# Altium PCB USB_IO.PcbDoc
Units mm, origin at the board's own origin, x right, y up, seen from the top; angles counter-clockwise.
Board outline 43.86 x 40 mm, 2 copper layers (Top Layer, Bottom Layer); 35 components, 51 nets, 147 pads, 74 vias.
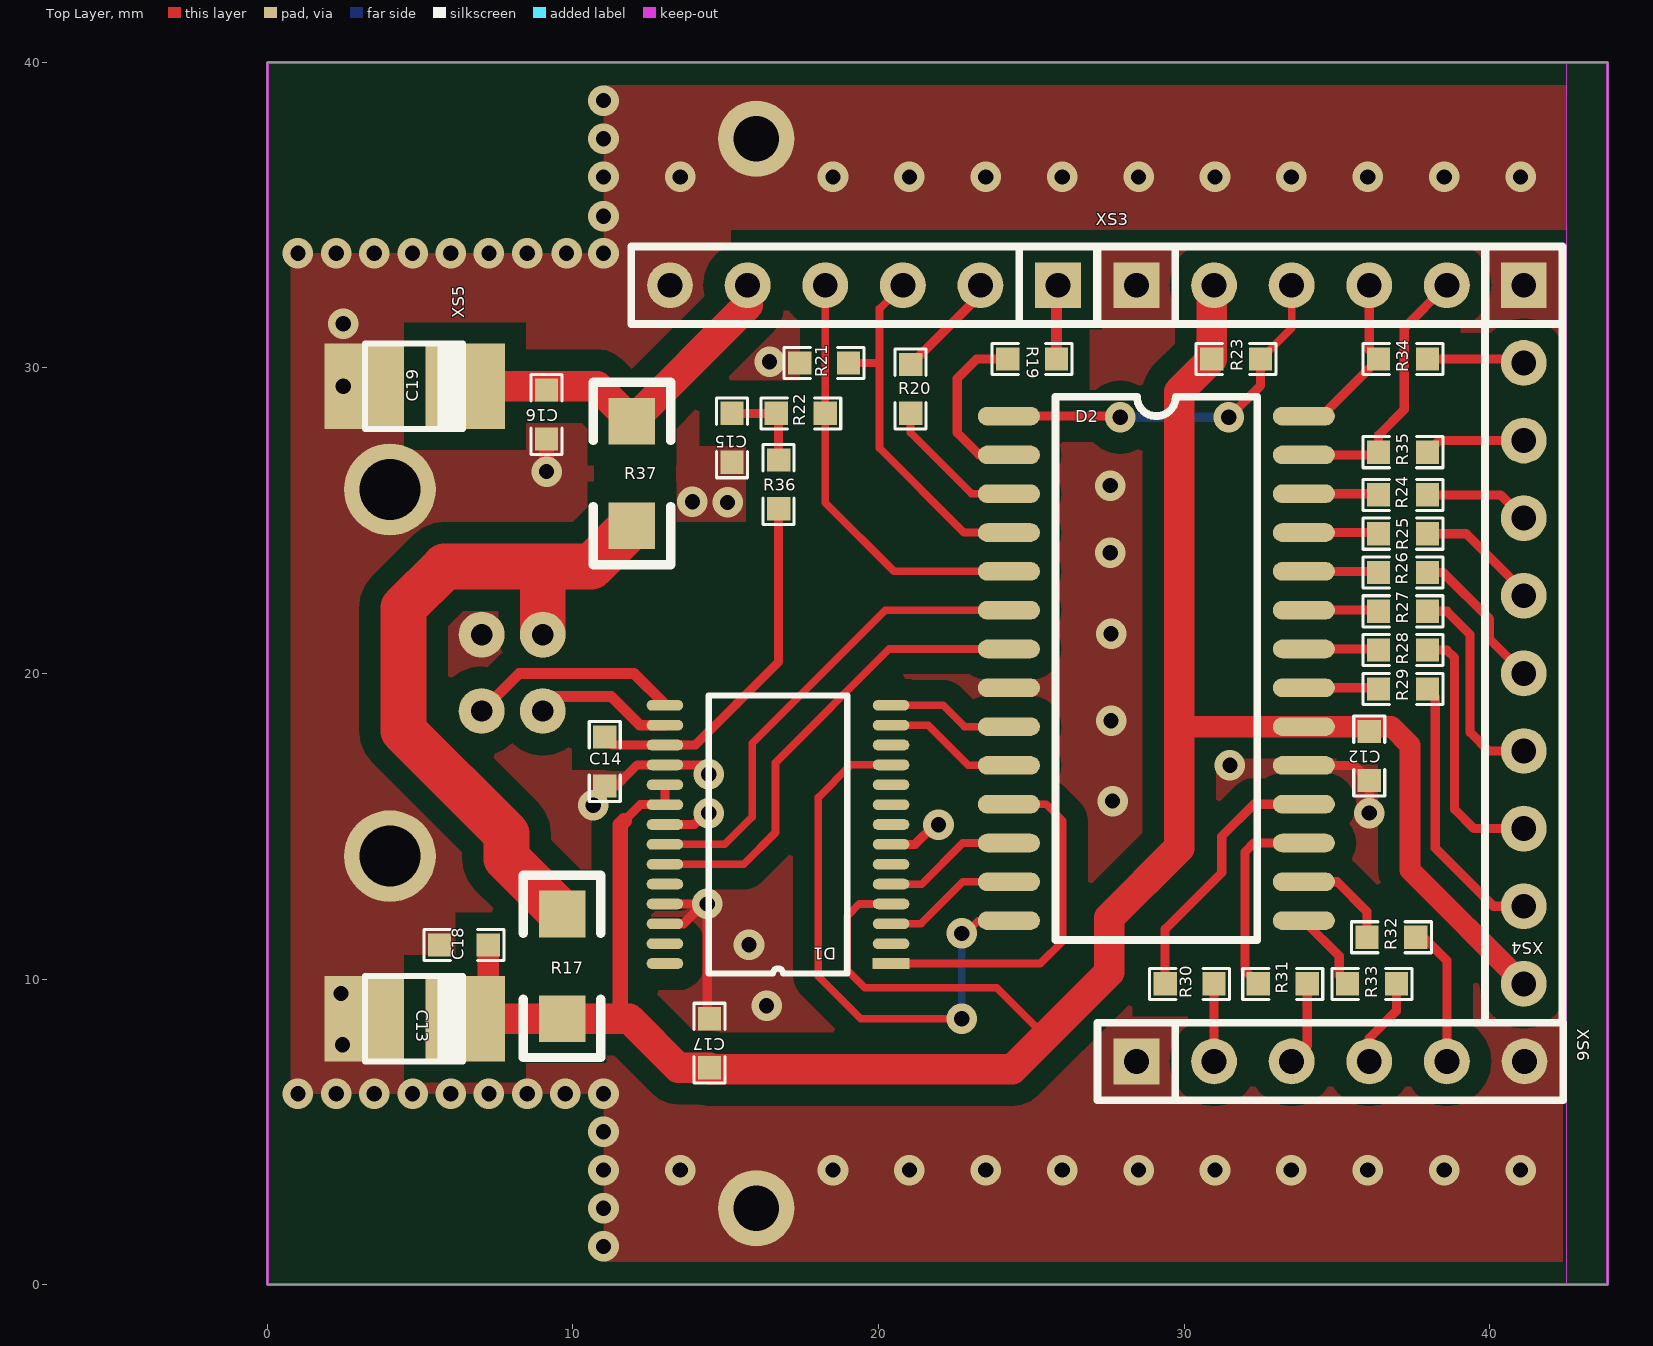
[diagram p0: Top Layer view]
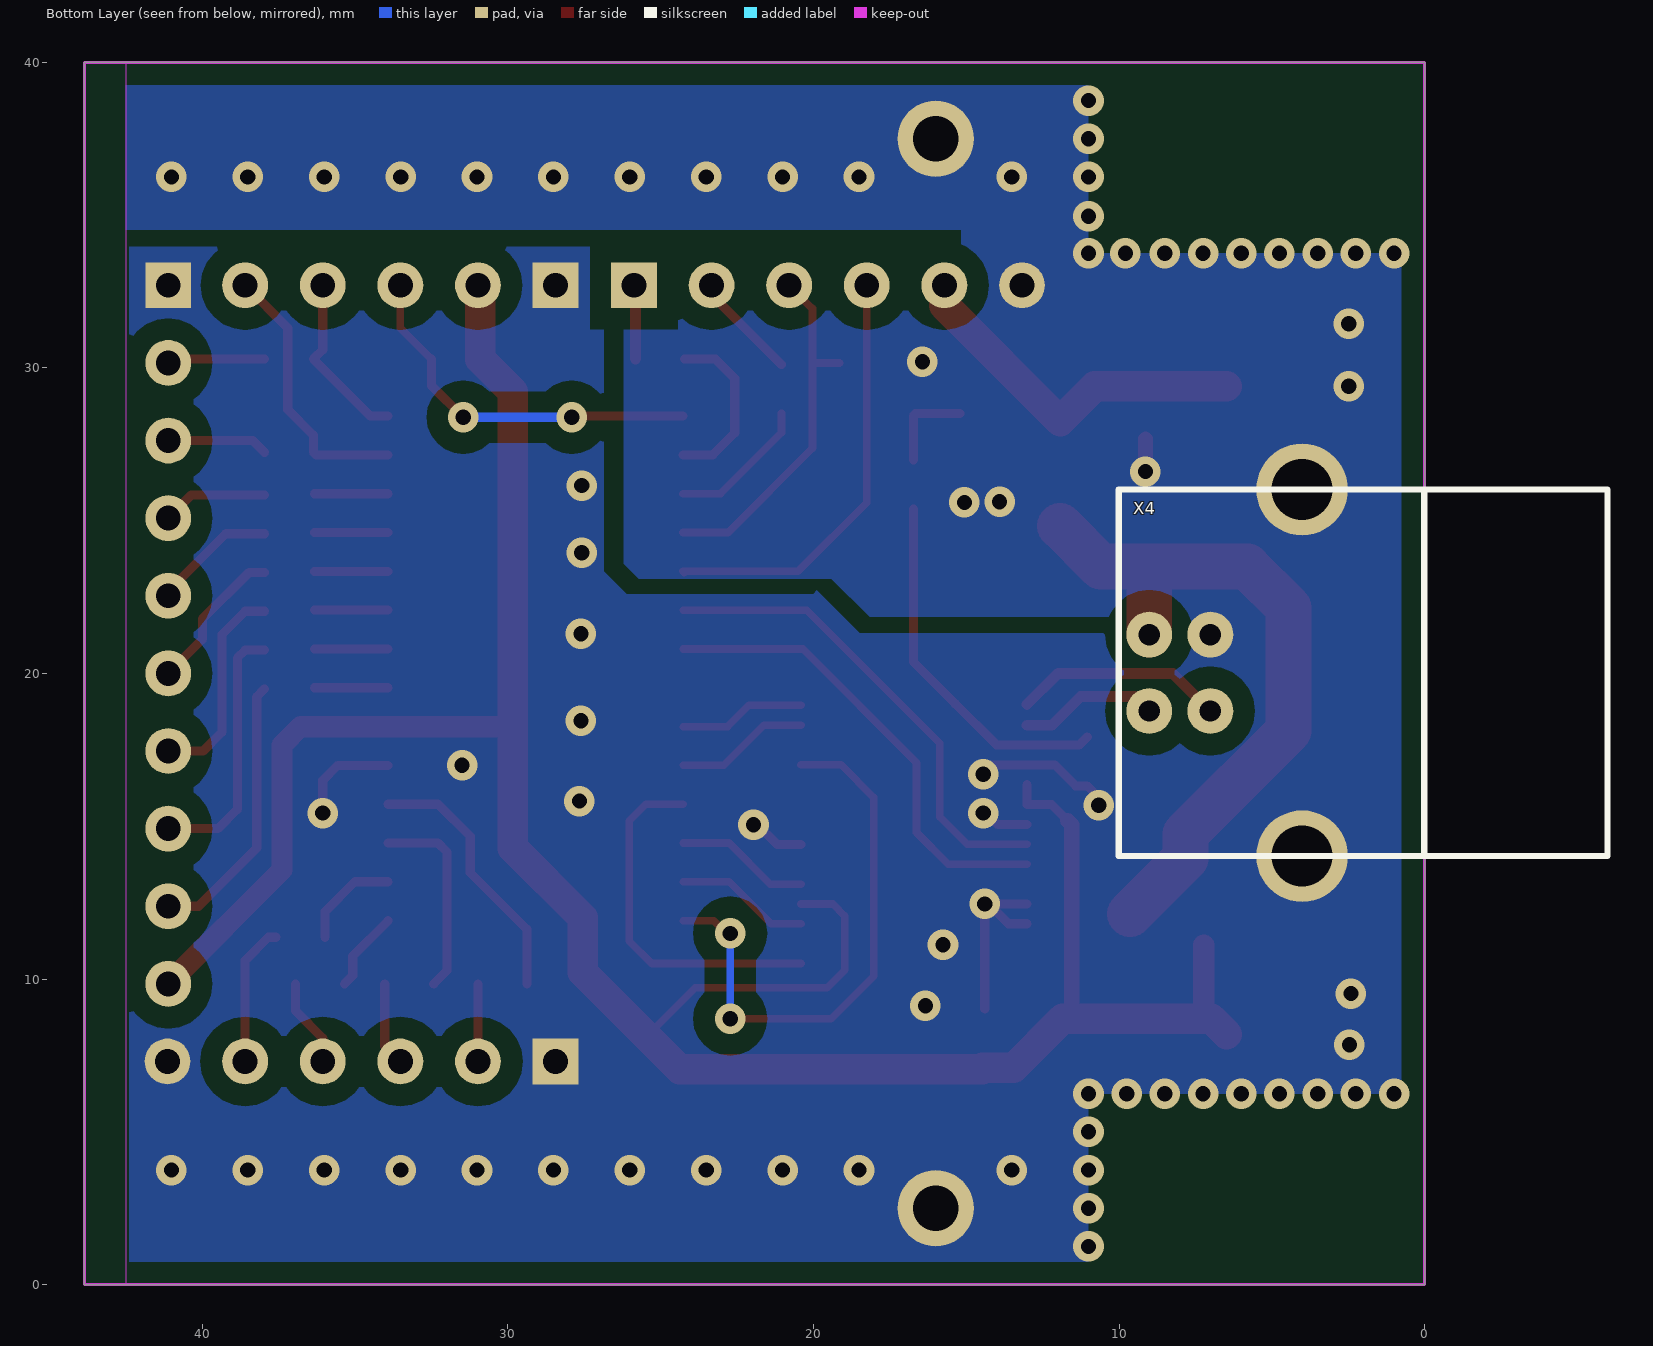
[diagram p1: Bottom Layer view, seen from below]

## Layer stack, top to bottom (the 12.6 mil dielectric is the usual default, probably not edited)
Top Solder: solder mask 0.0102, Solder Resist, Dk 3.5
Top Layer: signal copper 0.0356
Dielectric1: dielectric 0.32, FR-4, Dk 4.8
Bottom Layer: signal copper 0.0356
Bottom Solder: solder mask 0.0102, Solder Resist, Dk 3.5

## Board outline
0,0 0,40 43.861,40 43.861,0

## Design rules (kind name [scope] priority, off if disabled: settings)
AssemblyTestPointUsage [All] p1 off:
AssemblyTestpoint [All] p1 off: testpointundercomponent=TRUE minsize=1.016 maxsize=2.54 preferedsize=1.524 minholesize=0 maxholesize=1.016 preferedholesize=0.813 testpointgrid=0.025 usegrid=TRUE gridtolerance=0 allowsidetop=TRUE allowsidebottom=TRUE
Clearance Polygon1 [InPolygon] p1: gap=0.7
Clearance [All] p2: gap=0.2
ComponentClearance [All] p1 off: gap=0.254 collisioncheckmode=3 verticalgap=0.254 showdistances=FALSE
FabricationTestPointUsage TestPointUsage [All] p1: valid=0 allowmultiple=FALSE
FabricationTestpoint Testpoint [All] p1: side=3 testpointundercomponent=TRUE minsize=1.016 maxsize=2.54 preferedsize=1.524 minholesize=0.508 maxholesize=1.016 preferedholesize=0.813 testpointgrid=0.025 allowsidetop=TRUE allowsidebottom=TRUE usegrid=TRUE gridtolerance=0
HoleSize [All] p1: absolutevalues=TRUE maxlimit=6 minlimit=0.3 maxpercent=80.000 minpercent=20.000
HoleToHoleClearance [All] p1: gap=0.3 allowstackedmicrovias=TRUE
MinimumSolderMaskSliver [All] p1: minsoldermaskwidth=0.3
PolygonConnect [All] p1: connectstyle=Direct reliefconductorwidth=0.7 reliefentries=4 polygonreliefangle="90 Angle" airgapwidth=0.254
RoutingVias [All] p1: holewidth=0.5 width=1 viastyle="Through Hole" minholewidth=0.3 minwidth=0.7 maxholewidth=10 maxwidth=10
SilkToSilkClearance [All] p1 off: silktosilkclearance=0.254
SilkToSolderMaskClearance SilkscreenOverComponentPads [IsPad] p1 off: minsilkscreentomaskgap=0.254 clearancetoexposedcopper=TRUE
SolderMaskExpansion [All] p1: expansion=0.1
UnpouredPolygon [All] p1: allowunpoured=FALSE
Width [All] p1: maxlimit=10 minlimit=0.1 preferedwidth=0.5
19 further rules are at their usual default settings.

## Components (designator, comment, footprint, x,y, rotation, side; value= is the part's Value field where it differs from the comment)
C12 "100n" 0603 36.06,18.099 r270 top
C13 "47u 16V" FC_B 6.469,8.701 r180 top
C14 "1n" 0603 11.041,16.321 r90 top
C15 "----" 0603 15.208,28.513 r270 top
C16 "100n" 0603 9.136,29.275 r270 top
C17 "100n" 0603 14.47,8.701 r270 top
C18 "100n" 0603 7.231,11.114 r180 top
C19 "47u 16V" FC_B 6.469,29.402 r180 top
D1 "FT245R" SSOP-28 20.41,10.509 r180 top
D2 "PIC18F25K22" SOL-28 24.267,28.423 r0 top
R17 "0.47" 1206 9.644,8.701 r90 top
R19 "0R" 0603 24.225,30.291 r0 top
R20 "0R" 0603 21.05,28.513 r90 top
R21 "----" 0603 19.018,30.164 r180 top
R22 "----" 0603 18.256,28.513 r180 top
R23 "47K" 0603 32.504,30.291 r180 top
R24 "----" 0603 37.965,25.846 r180 top
R25 "----" 0603 37.965,24.576 r180 top
R26 "----" 0603 37.965,23.306 r180 top
R27 "----" 0603 37.965,22.036 r180 top
R28 "----" 0603 37.965,20.766 r180 top
R29 "----" 0603 37.965,19.496 r180 top
R30 "0R" 0603 30.98,9.844 r180 top
R31 "0R" 0603 34.028,9.844 r180 top
R32 "----" 0603 37.584,11.368 r180 top
R33 "----" 0603 36.949,9.844 r180 top
R34 "----" 0603 37.965,30.291 r180 top
R35 "----" 0603 37.965,27.243 r180 top
R36 "----" 0603 16.732,26.989 r270 top
R37 "0.47" 1206 11.93,28.259 r270 top
X4 "USB B" F_USB_B 3.916,14.031 r180 bottom
XS3 "PRG" SIP5 28.44,32.704 r0 top
XS4 "CONN_10" SIP-10 41.116,32.704 r270 top
XS5 "CONN_6" SIP-6 25.876,32.704 r180 top
XS6 "CONN_6" SIP-6 28.44,7.304 r0 top

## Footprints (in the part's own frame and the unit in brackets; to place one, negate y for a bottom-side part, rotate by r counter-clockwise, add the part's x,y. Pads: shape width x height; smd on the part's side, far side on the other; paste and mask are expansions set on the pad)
0603 [mil]
  rect 30x30 smd: 1(0,0) 2(63,0)
  silkscreen extent -20,-20 83,20
1206 [mil]
  rect 60x60 smd: 1(0,0) 2(135,0)
  silkscreen extent -50,-50 185,50
F_USB_B [mm]
  round 3 hole 2: 0(-0.095,-0.008) 0(-0.095,11.992)
  round 1.5 hole 0.7: 1(-5.095,7.242) 2(-5.095,4.742) 3(-3.095,4.742) 4(-3.095,7.242)
  silkscreen extent -6.09,-0.01 9.91,11.99
FC_B [mm]
  rect 2.6x2.8 smd: 1(0,0) 2(3.3,0)
  silkscreen extent 0.07,-1.4 3.27,1.4
SIP5 [mm]
  rect 1.5x1.5 hole 0.813: 1(0,0)
  round 1.5 hole 0.813: 2(2.54,0) 3(5.08,0) 4(7.62,0) 5(10.16,0)
  silkscreen extent -1.27,-1.27 11.43,1.27
SIP-6 [mm]
  rect 1.5x1.5 hole 0.813: 1(0,0)
  round 1.5 hole 0.813: 2(2.54,0) 3(5.08,0) 4(7.62,0) 5(10.16,0) 6(12.7,0)
  silkscreen extent -1.27,-1.27 13.97,1.27
SIP-10 [mm]
  rect 1.5x1.5 hole 0.813: 1(0,0)
  round 1.5 hole 0.813: 2(2.54,0) 3(5.08,0) 4(7.62,0) 5(10.16,0) 6(12.7,0) 7(15.24,0) 8(17.78,0) 9(20.32,0) 10(22.86,0)
  silkscreen extent -1.27,-1.27 24.13,1.27
SOL-28 [mil]
  oval 80x24 smd: 1(0,0) 2(0,-50) 3(0,-100) 4(0,-150) 5(0,-200) 6(0,-250) 7(0,-300) 8(0,-350) 9(0,-400) 10(0,-450) 11(0,-500) 12(0,-550) 13(0,-600) 14(0,-650) 15(380,-650) 16(380,-600) 17(380,-550) 18(380,-500) 19(380,-450) 20(380,-400) 21(380,-350) 22(380,-300) 23(380,-250) 24(380,-200) 25(380,-150) 26(380,-100) 27(380,-50) 28(380,0)
  silkscreen extent 60,-675 320,25
SSOP-28 [mm]
  rect 1.2x0.35 smd: 1(0,0)
  oval 1.2x0.35 smd: 2(0,-0.65) 3(0,-1.3) 4(0,-1.95) 5(0,-2.6) 6(0,-3.25) 7(0,-3.9) 8(0,-4.55) 9(0,-5.2) 10(0,-5.85) 11(0,-6.5) 12(0,-7.15) 13(0,-7.8) 14(0,-8.45) 15(7.4,-8.45) 16(7.4,-7.8) 17(7.4,-7.15) 18(7.4,-6.5) 19(7.4,-5.85) 20(7.4,-5.2) 21(7.4,-4.55) 22(7.4,-3.9) 23(7.4,-3.25) 24(7.4,-2.6) 25(7.4,-1.95) 26(7.4,-1.3) 27(7.4,-0.65) 28(7.4,0)
  silkscreen extent 1.43,-8.78 5.97,0.33

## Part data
C12 C14 C15 C16 C17 C18: library part C
C13 C19: library part C_E
D2: library part PIC18F2321
R17 R19 R20 R21 R22 R23 R24 R25 R26 R27 R28 R29 R30 R31 R32 R33 R34 R35 R36 R37: library part R_125
X4: library part CONN_4, "ТЕЛЕВИЗИОННЫЙ РАЗЪЕМ"
XS3: library part CONN_5, "ТЕЛЕВИЗИОННЫЙ РАЗЪЕМ"
XS4 XS5 XS6: "ТЕЛЕВИЗИОННЫЙ РАЗЪЕМ"

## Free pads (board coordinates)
  round 2.5 hole 1.5 mask+0: 4(16,37.5) 5(16,2.5)

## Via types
v1: diameter 1, hole 0.5, Top Layer to Bottom Layer, 73 vias
v2: diameter 1, hole 0.5, Top Layer to Bottom Layer, tented both sides, 1 vias

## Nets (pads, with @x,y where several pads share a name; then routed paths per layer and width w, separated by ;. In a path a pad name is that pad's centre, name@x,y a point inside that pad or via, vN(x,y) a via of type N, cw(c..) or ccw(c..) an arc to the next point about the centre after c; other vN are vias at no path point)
+3.3V: C15.1 R22.2 R36.1 | length 3
  Top Layer w0.3: C15.1 R22.2 16.732,28.437 R36.1
+5V: C12.1 C13.1 C17.2 C18.1 D1.4 D1.19 D1.20 D2.20 R17.1 R23.2 XS3.2 XS4.10 | length 85.7
  Top Layer w0.25: D1.4 19.371,12.459 18.975,12.063 18.975,10.292 19.55,9.717 23.868,9.717 25.328,8.257
  Top Layer w0.3: 11.676,15.178 12.207,15.709 D1.20 D1.19
  Top Layer w0.5: 11.549,8.75 11.549,15.051 11.676,15.178
  Top Layer w0.7: C13.1@7.231,8.955 C18.1 ; 29.927,18.263 D2.20 36.785,18.263 37.392,17.656 37.392,13.568 XS4.10
  Top Layer w1: C13.1@6.469,8.193 6.977,8.701 R17.1 11.849,8.701 13.449,7.101 C17.2 ; C17.2@14.47,7.05 24.376,7.05 27.551,10.225 27.551,12.003 29.837,14.289 29.837,29.224 R23.2 30.904,32.628 XS3.2
+5VANLG: C16.1 C19.1 R37.1 XS5.5 | length 11.9
  Top Layer w1: C19.1 10.787,29.402 R37.1 15.716,32.045 XS5.5
GND: C12.2 C13.2 C14.1 C15.2 C16.2 C17.1 C18.2 C19.2 D1.7 D1.18 D1.21 D1.25 D1.26 D2.8 D2.19 pad.4 pad.5 R21.2 X4.0 X4.4 XS3.1 XS4.1 XS5.6 XS6.1 XS6.6 | length 18.3
  Top Layer w0.3: v1(10.66,15.686) 10.66,15.94 C14.1 11.422,16.321 12.11,17.009 D1.18 v1@14.269,17.009 ; D1.26 13.618,11.809 14.268,12.459 D1.25 ; D1.21 13.97,15.059 v1@14.343,15.432 ; C17.1@14.395,9.03 v1(14.395,12.459) ; D1.7 21.194,14.409 21.836,15.051 v1(21.963,15.051) ; D2.19 35.566,16.993 C12.2 v1(36.06,15.432)
  Top Layer w0.5: v1(9.136,26.608) C16.2
  other v1: 11,1.25 11,2.5 11,3.75 13.511,3.75 18.511,3.75 21.011,3.75 23.511,3.75 26.011,3.75 28.511,3.75 31.011,3.75 33.511,3.75 36.011,3.75 38.511,3.75 41.011,3.75 11,5 1,6.25 2.25,6.25 3.5,6.25 4.75,6.25 6,6.25 7.25,6.25 8.5,6.25 9.75,6.25 11,6.25 2.461,7.85 16.336,9.125 2.411,9.525 15.761,11.125 14.445,15.432 27.661,15.825 14.445,16.702 27.611,18.45 27.611,21.3 27.586,23.95 15.061,25.6 13.911,25.625 27.586,26.15 2.486,29.4 16.436,30.2 2.486,31.45 1,33.75 2.25,33.75 3.5,33.75 4.75,33.75 6,33.75 7.25,33.75 8.5,33.75 9.79,33.75 11,33.75 11,34.96 11,36.25 13.511,36.25 18.511,36.25 21.011,36.25 23.511,36.25 26.011,36.25 28.511,36.25 31.011,36.25 33.511,36.25 36.011,36.25 38.511,36.25 41.011,36.25 11,37.5 11,38.75
  other v2: 31.5,17
NetC14_2: C14.2 D1.17 R36.2 | length 11.9
  Top Layer w0.3: C14.2 11.303,17.659 D1.17 14.005,17.659 15.359,19.013 16.732,20.386 R36.2
NetD2_2: D2.2 R19.1 | length 5.7
  Top Layer w0.3: R19.1 23.209,30.291 22.574,29.656 22.574,27.878 23.299,27.153 D2.2
NetD2_3: D2.3 R20.1 | length 4.7
  Top Layer w0.253: R20.1 21.05,27.878 23.045,25.883 D2.3
NetD2_15: D2.15 R33.2 | length 2.7
  Top Layer w0.3: D2.15 35.076,10.756 35.076,10.116 R33.2
NetD2_16: D2.16 R32.2 | length 3.3
  Top Layer w0.3: D2.16 35.007,13.183 35.984,12.206 R32.2
NetD2_17: D2.17 R31.2 | length 6.5
  Top Layer w0.3: R31.2 31.996,10.276 31.996,14.162 32.287,14.453 D2.17
NetD2_18: D2.18 R30.2 | length 8.7
  Top Layer w0.3: R30.2 29.38,11.63 31.234,13.484 31.234,14.67 32.287,15.723 D2.18
NetD2_21: D2.21 R29.2 | length 2.4
  Top Layer w0.3: D2.21 R29.2@36.328,19.533
NetD2_22: D2.22 R28.2 | length 2.4
  Top Layer w0.3: D2.22 R28.2@36.328,20.803
NetD2_23: D2.23 R27.2 | length 2.4
  Top Layer w0.3: D2.23 R27.2@36.328,22.073
NetD2_24: D2.24 R26.2 | length 2.4
  Top Layer w0.3: D2.24 R26.2@36.328,23.343
NetD2_25: D2.25 R25.2 | length 2.4
  Top Layer w0.3: D2.25 R25.2@36.328,24.613
NetD2_26: D2.26 R24.2 | length 2.4
  Top Layer w0.3: D2.26 R24.2@36.328,25.883
NetR17_2: R17.2 R37.2 X4.1 | length 23
  Top Layer w1.5: X4.1 9.011,23.5 ; R17.2 7.825,13.949 7.825,14.75 4.45,18.125 4.45,22.15 5.8,23.5 9.011,23.5 ; R37.2 10.6,23.5 9.011,23.5
P_A0: R19.2 XS5.1 | length 2.4
  Top Layer w0.35: R19.2 XS5.1@25.825,32.653
P_A1: R20.2 XS5.2 | length 3.5
  Top Layer w0.3: R20.2 23.336,32.399 XS5.2
P_A2: D2.4 R21.1 XS5.3 | length 11.9
  Top Layer w0.253: R21.1@19.145,30.164 20.034,30.164 ; XS5.3 20.034,31.942 20.034,30.164 ; D2.4 22.791,24.613 20.034,27.37 20.034,30.164
P_A3: D2.5 R22.1 XS5.4 | length 14.1
  Top Layer w0.253: XS5.4 18.256,25.592 20.505,23.343 D2.5 D2.5@24.23,23.306
P_B0: R29.1 XS4.9 | length 9
  Top Layer w0.3: R29.1 38.219,19.242 38.219,14.289 40.124,12.384 XS4.9
P_B1: R28.1 XS4.8 | length 8.5
  Top Layer w0.3: R28.1 38.6,20.766 38.854,20.512 38.854,15.559 39.489,14.924 XS4.8
P_B2: R27.1 XS4.7 | length 6.9
  Top Layer w0.3: R27.1 38.6,22.036 39.362,21.274 39.362,18.075 39.973,17.464 XS4.7
P_B3: R26.1 XS4.6 | length 4.9
  Top Layer w0.3: R26.1 38.473,23.306 39.997,21.782 39.997,21.123 XS4.6
P_B4: R25.1 XS4.5 | length 4.1
  Top Layer w0.3: R25.1 39.235,24.576 41.116,22.695 XS4.5
P_B5: R24.1 XS4.4 | length 3.5
  Top Layer w0.3: R24.1 40.354,25.846 XS4.4
P_B6: R35.1 XS4.3 | length 3.3
  Top Layer w0.3: R35.1 38.346,27.624 XS4.3
P_B7: R34.1 XS4.2 | length 3.2
  Top Layer w0.3: R34.1 40.989,30.291 XS4.2
P_C4: R33.1 XS6.4 | length 2.9
  Top Layer w0.3: XS6.4 36.06,8.066 36.949,8.955 R33.1
P_C5: R32.1 XS6.5 | length 4.6
  Top Layer w0.3: R32.1 37.838,11.368 38.6,10.606 XS6.5
P_C6: R31.1 XS6.3 | length 2.8
  Top Layer w0.3: XS6.3 34.028,7.812 R31.1
P_C7: R30.1 XS6.2 | length 2.5
  Top Layer w0.3: XS6.2 R30.1
P_D0: D1.1 D2.11 | length 11.8
  Top Layer w0.25: D1.1 25.295,10.509 26.027,11.241 26.027,15.178 25.482,15.723 D2.11
P_D1: D1.5 D2.12 | length 4.4
  Top Layer w0.25: D1.5 21.418,13.109 22.762,14.453 D2.12
P_D2: D1.3 D2.13 | length 4.4
  Top Layer w0.25: D1.3 21.388,11.809 22.762,13.183 D2.13
P_D3: D1.11 D2.14 | length 18.1
  Top Layer w0.25: D1.11 19.095,17.009 18.026,15.94 18.026,10.098 19.423,8.701 v1(22.725,8.701) ; v1@22.725,11.368 23.27,11.913 D2.14
  Bottom Layer w0.25: v1@22.725,8.955 v1@22.725,11.368
  other v1: 22.725,11.495
P_D4: D1.2
P_D5: D1.9
P_D6: D1.10
P_D7: D1.6
P_D+: D1.15 X4.3 | length 7
  Top Layer w0.3: D1.15 D1.15@13.01,18.99
  Top Layer w0.35: X4.3 8.238,20 12,20 D1.15@13.01,18.99
P_D-: D1.16 X4.2 | length 4.6
  Top Layer w0.35: X4.2 9.488,19.25 11.25,19.25 12.191,18.309 D1.16
P_FTRD: D1.13 D2.10 | length 4.4
  Top Layer w0.25: D1.13 21.626,18.309 22.942,16.993 D2.10
P_FTRXF: D1.23 D2.7 | length 15.5
  Top Layer w0.25: D1.23 15.591,13.759 16.629,14.797 16.629,17.083 20.349,20.803 D2.7
P_FTTXE: D1.22 D2.6 | length 15.8
  Top Layer w0.25: D1.22 14.971,14.409 15.867,15.305 15.867,17.718 20.222,22.073 D2.6
P_FTWR: D1.14 D2.9 | length 4.1
  Top Layer w0.25: D1.14 22.119,18.959 22.815,18.263 D2.9
P_PGC: D2.27 R35.2 XS3.5 | length 8.9
  Top Layer w0.3: D2.27 36.275,27.153 R35.2 36.365,27.802 37.203,28.64 37.203,31.307 XS3.5
P_PGD: D2.28 R34.2 XS3.4 | length 6.1
  Top Layer w0.3: D2.28@34.243,28.423 D2.28 34.497,28.423 R34.2 36.06,30.596 XS3.4
P_VPP: D2.1 R23.1 XS3.3 | length 12.4
  Top Layer w0.253: R23.1 33.52,31.307 XS3.3
  Top Layer w0.3: D2.1 27.871,28.423 v1(27.908,28.386) ; v1(31.464,28.386) 32.504,29.426 R23.1
  Bottom Layer w0.3: v1(27.908,28.386) v1(31.464,28.386)
pads on no net: D1.8 D1.12 D1.24 D1.27 D1.28

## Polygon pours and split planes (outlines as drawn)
GND on Bottom Layer "B_GND" (solid, remove dead copper, pour order 1000): 11,0 43.65,0 43.65,40 11,40 11,33.75 0,33.75 0,6.25 11,6.25
GND on Top Layer "T_GND" (solid, remove dead copper, pour order 1001): 0,6.25 5.902,0 38.098,0 40.266,0.103 41.451,0 44,0 44,40 38.098,40 11,40 11,33.75 0,33.75

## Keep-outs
Keep-Out Layer:
  pour cut-out: 42.5,40 42.5,0 43.861,0 43.861,40
  lines w0.1: 0,0 0,40 43.861,40 43.861,0 0,0

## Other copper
Top Layer:
  pour cut-out: 11,6.25 0.75,6.25 0.5,6 0.5,0 11,0
  pour cut-out: 15.775,22.148 15.775,24.908 15.711,24.973 13.086,24.973 13.086,22.148
  pour cut-out: 13.375,25.162 13.375,27.923 13.311,27.988 10.686,27.988 10.686,25.162
  pour cut-out: 15.161,33.974 42.386,33.974 42.386,0 42.861,0 42.861,34.163 42.711,34.525 15.161,34.525
Bottom Layer:
  pour cut-out: 15.161,33.974 42.386,33.974 42.386,0 42.861,0 42.861,34.375 42.711,34.525 15.161,34.525
  pour cut-out: 9.836,21.325 18.486,21.325 19.886,22.725 20.011,22.6 26.111,22.6 26.86,23.349 26.86,31.41 26.836,31.434 26.211,31.434 26.211,23.595 25.716,23.1 19.411,23.1 18.161,21.85 9.886,21.85 9.836,21.9

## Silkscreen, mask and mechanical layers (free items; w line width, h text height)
Top Overlay:
  text "FR4 H=0.7mm t=0.035mm" at 0.3,42 h2 r0.06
